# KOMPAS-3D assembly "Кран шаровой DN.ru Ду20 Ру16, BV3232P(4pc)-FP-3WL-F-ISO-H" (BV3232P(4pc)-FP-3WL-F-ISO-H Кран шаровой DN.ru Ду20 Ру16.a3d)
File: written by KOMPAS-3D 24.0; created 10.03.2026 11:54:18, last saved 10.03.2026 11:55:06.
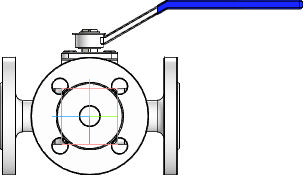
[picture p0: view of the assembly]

Document properties: Автор: R2D2; Полное имя файла: E:\Работа\Зайцев\BV3232P(4pc)-FP-3WL-F-ISO-H Кран шаровой DN.ru Ду15-100 Ру16\DN20\исходные материалы\BV3232P(4pc)-FP-3WL-F-ISO-H Кран шаровой DN.ru Ду20 Ру16.a3d

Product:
- Component [assembly]: Сборка1  | qty 1  | Масса: 4.915075; Автор: R2D2; source file: dn20_3d_step.a3d
- Part/product: Кран шаровой DN.ru Ду20 Ру16  | designation BV3232P(4pc)-FP-3WL-F-ISO-H
    Масса: 4.5
    Раздел спецификации: Прочие изделия
    Примечание: D160-36356

Referenced files in E:\Работа\Зайцев\BV3232P(4pc)-FP-3WL-F-ISO-H Кран шаровой DN.ru Ду15-100 Ру16\DN20\исходные материалы\: dn20_3d_step.a3d
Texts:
  BV3232P(4pc)-FP-3WL-F-ISO-H
  Сборка1 Сборка1
  Ось Z.Начало координат
  Ось Y.Начало координат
